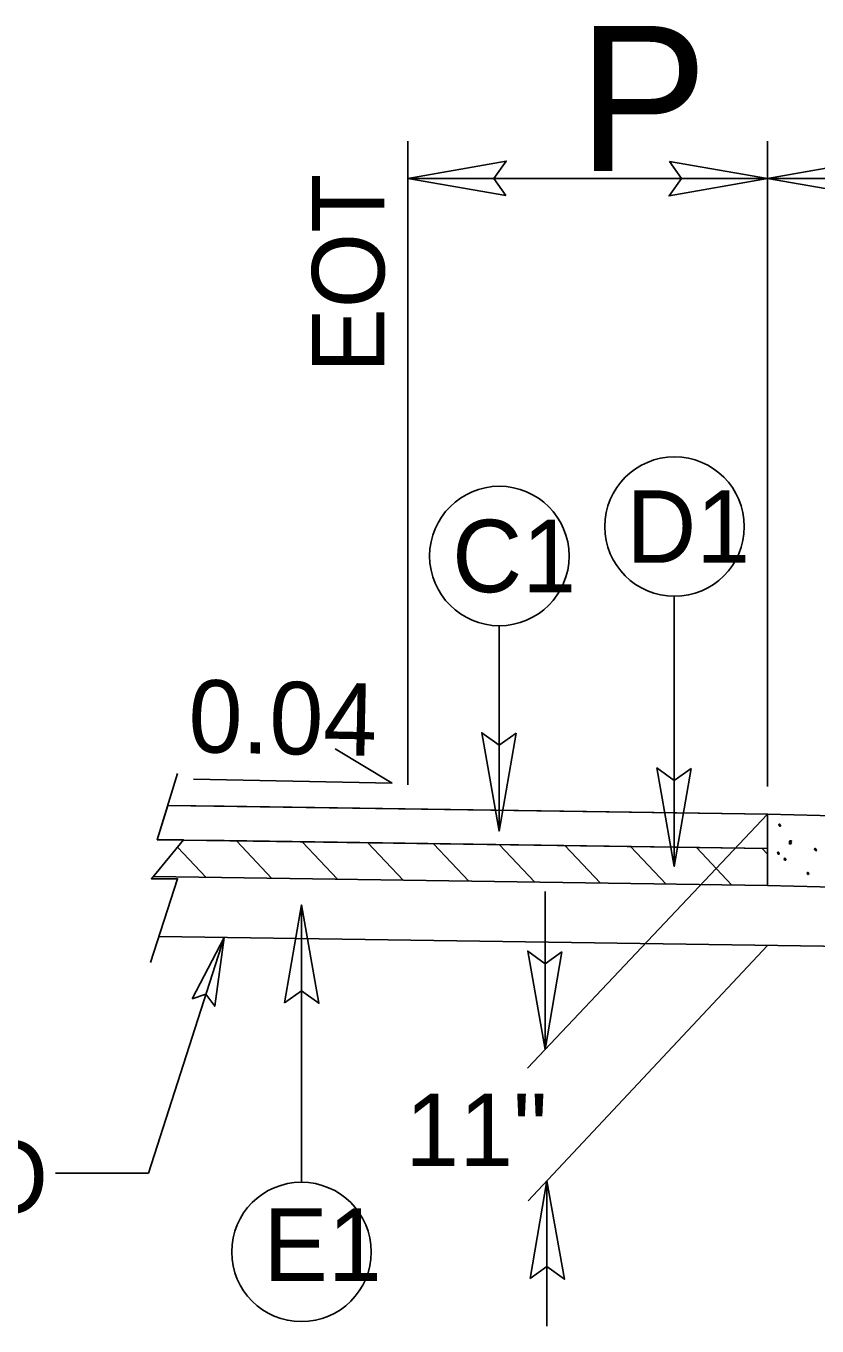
# Model space of a CAD drawing. Extents: x 1553884 to 1554215, y 810431 to 810779.
# Drawn here: x 1554035.12 to 1554046.03, y 810663.82 to 810681.75 of the extents above; entities that cross this region are included whole.
import ezdxf

# ---------------------------------------------------------------- set-up
doc = ezdxf.new("R2010")
doc.units = 0
for name, color, linetype in [('Old_Level_1', 7, 'Continuous'), ('Old_Level_15', 7, 'Continuous'), ('Old_Level_3', 7, 'Continuous'), ('Prop CMT Steel Beam Girder', 7, 'Continuous'), ('Prop Shade Light', 7, 'Continuous'), ('Typical Arrow Superelevation CELL', 7, 'Continuous'), ('Typical Detail Pavement Repair CELL', 7, 'Continuous'), ('Typical Pavement Slope Information CELL', 7, 'Continuous'), ('Typical Text ID Circle CELL', 7, 'Continuous')]:
    doc.layers.add(name, color=color, linetype=linetype)

msp = doc.modelspace()

# ---------------------------------------------------------------- linework, layer by layer
at = {"layer": 'Old_Level_1'}
for p, q in [((1554040.385, 810680.165), (1554040.385, 810671.284)), ((1554045.346, 810680.165), (1554045.346, 810671.26)), ((1554040.385, 810679.651), (1554045.346, 810679.651)), ((1554045.346, 810679.651), (1554050.307, 810679.651)), ((1554037.851, 810670.988), (1554037.072, 810670.999)), ((1554037.851, 810670.988), (1554037.851, 810670.981)), ((1554045.346, 810670.879), (1554037.851, 810670.988)), ((1554045.346, 810670.879), (1554042.033, 810667.371)), ((1554045.508, 810670.74), (1554045.504, 810670.734)), ((1554045.504, 810670.734), (1554045.504, 810670.731)), ((1554045.504, 810670.731), (1554045.507, 810670.731)), ((1554045.507, 810670.731), (1554045.508, 810670.718)), ((1554045.516, 810670.739), (1554045.508, 810670.74)), ((1554045.508, 810670.718), (1554045.516, 810670.712)), ((1554045.522, 810670.733), (1554045.511, 810670.737)), ((1554045.521, 810670.734), (1554045.516, 810670.739)), ((1554045.516, 810670.712), (1554045.527, 810670.714)), ((1554045.527, 810670.715), (1554045.522, 810670.733)), ((1554045.527, 810670.714), (1554045.527, 810670.715)), ((1554037.206, 810670.425), (1554037.602, 810670.005)), ((1554045.346, 810670.404), (1554037.284, 810670.521)), ((1554038.019, 810670.511), (1554038.509, 810669.992)), ((1554038.926, 810670.497), (1554039.415, 810669.979)), ((1554039.832, 810670.484), (1554040.321, 810669.966)), ((1554040.738, 810670.471), (1554041.228, 810669.953)), ((1554041.645, 810670.458), (1554042.134, 810669.939)), ((1554042.551, 810670.445), (1554043.041, 810669.926)), ((1554043.458, 810670.432), (1554043.947, 810669.913)), ((1554044.364, 810670.418), (1554044.853, 810669.9)), ((1554045.27, 810670.405), (1554045.346, 810670.325)), ((1554045.648, 810670.468), (1554045.649, 810670.484)), ((1554045.651, 810670.465), (1554045.648, 810670.468)), ((1554045.649, 810670.484), (1554045.651, 810670.486)), ((1554045.651, 810670.5), (1554045.655, 810670.508)), ((1554045.651, 810670.501), (1554045.654, 810670.508)), ((1554045.654, 810670.508), (1554045.651, 810670.492)), ((1554045.654, 810670.486), (1554045.651, 810670.501)), ((1554045.651, 810670.481), (1554045.651, 810670.5)), ((1554045.651, 810670.486), (1554045.654, 810670.486)), ((1554045.663, 810670.468), (1554045.651, 810670.465)), ((1554045.655, 810670.508), (1554045.668, 810670.512)), ((1554045.671, 810670.473), (1554045.663, 810670.468)), ((1554045.668, 810670.512), (1554045.674, 810670.512)), ((1554045.669, 810670.498), (1554045.668, 810670.495)), ((1554045.668, 810670.495), (1554045.669, 810670.493)), ((1554045.677, 810670.5), (1554045.669, 810670.498)), ((1554045.669, 810670.493), (1554045.676, 810670.481)), ((1554045.676, 810670.481), (1554045.671, 810670.473)), ((1554045.674, 810670.512), (1554045.677, 810670.508)), ((1554045.677, 810670.508), (1554045.677, 810670.5)), ((1554045.997, 810670.406), (1554045.994, 810670.4)), ((1554045.994, 810670.4), (1554045.994, 810670.395)), ((1554045.994, 810670.395), (1554045.996, 810670.395)), ((1554045.996, 810670.395), (1554045.997, 810670.384)), ((1554046.007, 810670.404), (1554045.997, 810670.406)), ((1554046.001, 810670.395), (1554046.001, 810670.391)), ((1554046.013, 810670.398), (1554046.002, 810670.401)), ((1554046.01, 810670.4), (1554046.007, 810670.404)), ((1554046.018, 810670.394), (1554046.008, 810670.397)), ((1554046.016, 810670.381), (1554046.013, 810670.398)), ((1554046.023, 810670.377), (1554046.018, 810670.394)), ((1554045.488, 810670.354), (1554045.485, 810670.348)), ((1554045.485, 810670.348), (1554045.485, 810670.345)), ((1554045.485, 810670.345), (1554045.487, 810670.345)), ((1554045.487, 810670.345), (1554045.488, 810670.333)), ((1554045.497, 810670.353), (1554045.488, 810670.354)), ((1554045.488, 810670.333), (1554045.497, 810670.326)), ((1554045.504, 810670.347), (1554045.493, 810670.351)), ((1554045.501, 810670.348), (1554045.497, 810670.353)), ((1554045.497, 810670.326), (1554045.507, 810670.328)), ((1554045.507, 810670.331), (1554045.504, 810670.347)), ((1554045.507, 810670.328), (1554045.507, 810670.331)), ((1554045.58, 810670.27), (1554045.576, 810670.264)), ((1554045.576, 810670.264), (1554045.576, 810670.261)), ((1554045.576, 810670.261), (1554045.577, 810670.261)), ((1554045.577, 810670.261), (1554045.58, 810670.248)), ((1554045.588, 810670.269), (1554045.58, 810670.27)), ((1554045.58, 810670.248), (1554045.588, 810670.242)), ((1554045.594, 810670.262), (1554045.583, 810670.267)), ((1554045.591, 810670.264), (1554045.588, 810670.269)), ((1554045.588, 810670.242), (1554045.598, 810670.244)), ((1554045.598, 810670.247), (1554045.594, 810670.262)), ((1554045.598, 810670.244), (1554045.598, 810670.247)), ((1554045.997, 810670.384), (1554046.007, 810670.378)), ((1554046.001, 810670.391), (1554046.002, 810670.391)), ((1554046.002, 810670.391), (1554046.004, 810670.38)), ((1554046.004, 810670.38), (1554046.013, 810670.373)), ((1554046.007, 810670.378), (1554046.016, 810670.379)), ((1554046.013, 810670.373), (1554046.023, 810670.375)), ((1554046.016, 810670.379), (1554046.016, 810670.381)), ((1554046.023, 810670.375), (1554046.023, 810670.377)), ((1554045.897, 810670.075), (1554045.894, 810670.069)), ((1554045.894, 810670.069), (1554045.894, 810670.064)), ((1554045.894, 810670.064), (1554045.896, 810670.064)), ((1554045.896, 810670.064), (1554045.897, 810670.051)), ((1554045.907, 810670.073), (1554045.897, 810670.075)), ((1554045.897, 810670.051), (1554045.907, 810670.047)), ((1554045.913, 810670.067), (1554045.902, 810670.07)), ((1554045.91, 810670.069), (1554045.907, 810670.073)), ((1554045.907, 810670.047), (1554045.916, 810670.048)), ((1554045.916, 810670.05), (1554045.913, 810670.067)), ((1554045.916, 810670.048), (1554045.916, 810670.05)), ((1554045.346, 810669.893), (1554036.872, 810670.016)), ((1554042.278, 810669.813), (1554042.278, 810667.63)), ((1554058.463, 810668.877), (1554036.949, 810669.189)), ((1554045.346, 810669.067), (1554042.045, 810665.542)), ((1554042.304, 810663.815), (1554042.304, 810665.819))]:
    msp.add_line(p, q, dxfattribs=at)
msp.add_lwpolyline([(1554036.833, 810668.832), (1554037.208, 810669.987), (1554036.848, 810669.987), (1554037.289, 810670.526), (1554036.929, 810670.526), (1554037.205, 810671.44)], dxfattribs=at)
at = {"layer": 'Old_Level_15'}
msp.add_lwpolyline([(1554037.411, 810668.332), (1554037.851, 810669.175), (1554037.722, 810668.227), (1554037.6, 810668.392)], close=True, dxfattribs=at)
at = {"layer": 'Old_Level_3'}
msp.add_lwpolyline([(1554037.072, 810670.999), (1554045.346, 810670.879), (1554045.346, 810670.404), (1554037.851, 810670.513), (1554037.284, 810670.521), (1554037.289, 810670.526), (1554036.929, 810670.526)], close=True, dxfattribs=at)
at = {"layer": 'Prop CMT Steel Beam Girder'}
for p, q in [((1554044.06, 810670.158), (1554044.06, 810673.885)), ((1554041.644, 810670.644), (1554041.644, 810673.48)), ((1554038.917, 810669.626), (1554038.917, 810665.799))]:
    msp.add_line(p, q, dxfattribs=at)
at = {"layer": 'Prop Shade Light'}
for p, q in [((1554045.346, 810669.893), (1554045.346, 810670.879)), ((1554045.346, 810670.879), (1554050.52, 810670.748)), ((1554045.346, 810669.893), (1554051.595, 810669.734))]:
    msp.add_line(p, q, dxfattribs=at)
at = {"layer": 'Typical Arrow Superelevation CELL'}
for p, q in [((1554040.167, 810671.304), (1554039.384, 810671.778)), ((1554040.167, 810671.304), (1554037.428, 810671.359)), ((1554036.807, 810665.926), (1554037.851, 810669.175)), ((1554035.524, 810665.926), (1554036.807, 810665.926))]:
    msp.add_line(p, q, dxfattribs=at)
at = {"layer": 'Typical Pavement Slope Information CELL'}
for points in [[(1554041.735, 810679.418), (1554040.385, 810679.651), (1554041.742, 810679.891), (1554041.57, 810679.651)], [(1554043.996, 810679.883), (1554045.346, 810679.651), (1554043.988, 810679.411), (1554044.161, 810679.651)], [(1554046.696, 810679.418), (1554045.346, 810679.651), (1554046.703, 810679.891), (1554046.531, 810679.651)], [(1554041.877, 810671.994), (1554041.644, 810670.644), (1554041.404, 810672.001), (1554041.644, 810671.829)], [(1554044.293, 810671.508), (1554044.06, 810670.158), (1554043.82, 810671.516), (1554044.06, 810671.343)], [(1554038.684, 810668.276), (1554038.917, 810669.626), (1554039.157, 810668.268), (1554038.917, 810668.441)], [(1554042.51, 810668.98), (1554042.278, 810667.63), (1554042.038, 810668.988), (1554042.278, 810668.815)], [(1554042.071, 810664.469), (1554042.304, 810665.819), (1554042.544, 810664.461), (1554042.304, 810664.634)]]:
    msp.add_lwpolyline(points, close=True, dxfattribs=at)
at = {"layer": 'Typical Text ID Circle CELL'}
for centre in [(1554044.064, 810674.847), (1554041.647, 810674.441), (1554038.917, 810664.837)]:
    msp.add_circle(centre, 0.962, dxfattribs=at)

# ---------------------------------------------------------------- texts
at = {"layer": 'Old_Level_1'}
for s, rotation, p in [('EOT', 90, (1554040.062, 810676.968)), ('0.04', 358.7999, (1554037.35, 810671.735))]:
    msp.add_text(s, height=1, rotation=rotation, dxfattribs=at).set_placement(p)
msp.add_text('11"', height=1, dxfattribs=at).set_placement((1554040.349, 810666.021))
at = {"layer": 'Typical Arrow Superelevation CELL'}
for s, height, p in [('P', 2, (1554042.735, 810679.755)), ('GRADE TO', 1, (1554028.438, 810665.373))]:
    msp.add_text(s, height=height, dxfattribs=at).set_placement(p)
at = {"layer": 'Typical Detail Pavement Repair CELL'}
for s, p in [('D1', (1554043.397, 810674.347)), ('C1', (1554040.996, 810673.941)), ('E1', (1554038.39, 810664.437))]:
    msp.add_text(s, height=1, dxfattribs=at).set_placement(p)

doc.saveas('drawing.dxf')
